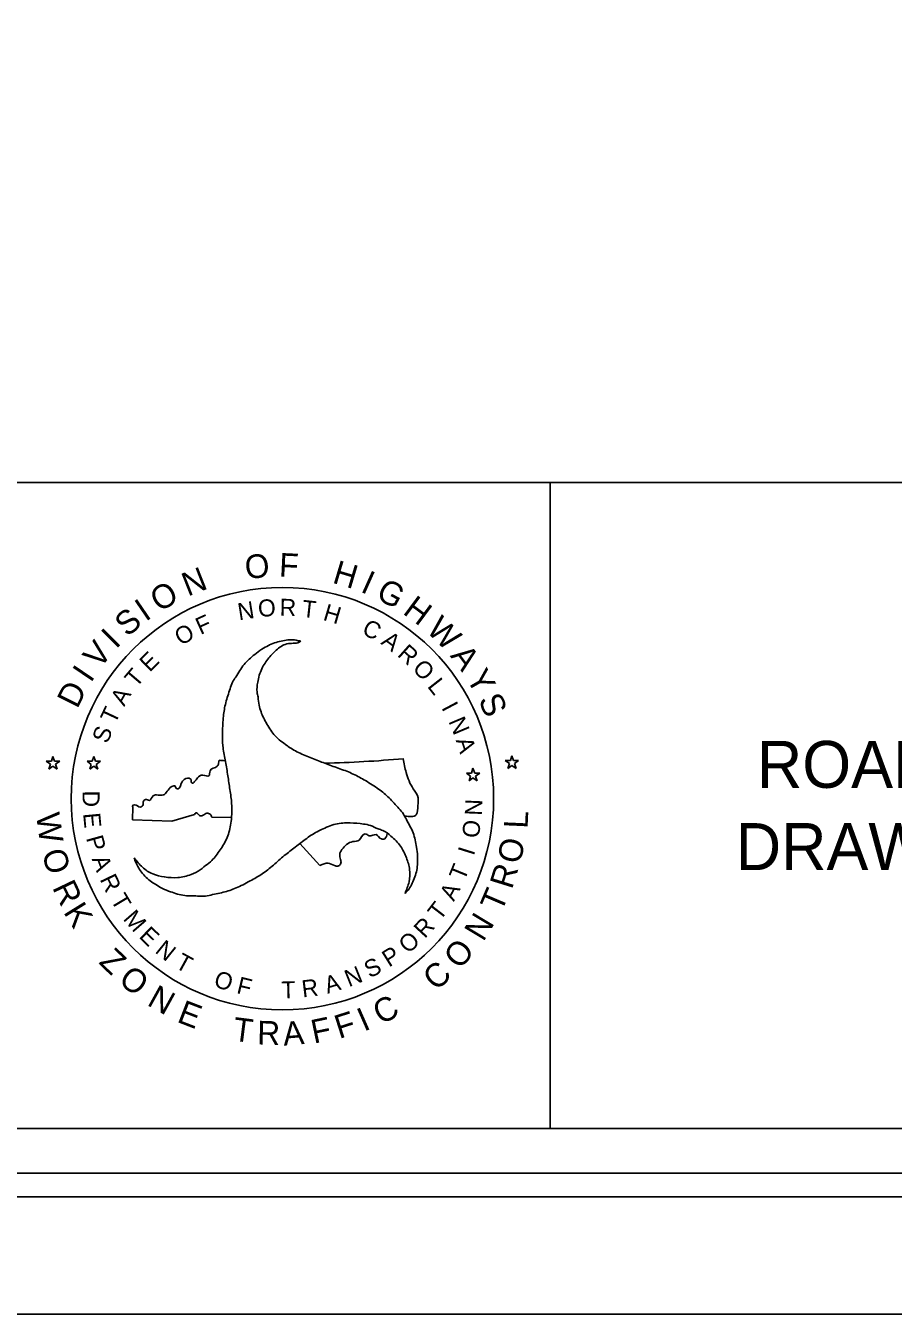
# Model space of a CAD drawing. Extents: x 198 to 2213, y -571 to 529.
# Drawn here: x 1502.9 to 1687.6, y -570.9 to -296.6 of the extents above; entities that cross this region are included whole.
import ezdxf

# ---------------------------------------------------------------- set-up
doc = ezdxf.new("R2010")
doc.units = 0
for name, color, linetype in [('P_RDY_Dimension', 7, 'Continuous'), ('Sheet Data Field CELL', 7, 'Continuous'), ('Sheet PE Seal CELL', 7, 'Continuous'), ('z - Construction', 7, 'Continuous')]:
    doc.layers.add(name, color=color, linetype=linetype)

msp = doc.modelspace()

# ---------------------------------------------------------------- linework, layer by layer
at = {"layer": 'P_RDY_Dimension'}
for p, q in [((1508.64, -452.14), (1508.32, -453.15)), ((1509, -453.15), (1508.64, -452.14)), ((1517.32, -452.16), (1517, -453.16)), ((1517.68, -453.16), (1517.32, -452.16)), ((1606.36, -452), (1606.04, -453.01)), ((1606.72, -453.01), (1606.36, -452)), ((1507.23, -453.15), (1508.12, -453.79)), ((1508.32, -453.15), (1507.23, -453.15)), ((1508.12, -453.79), (1507.8, -454.83)), ((1507.8, -454.83), (1508.64, -454.19)), ((1508.64, -454.19), (1509.53, -454.83)), ((1508.64, -454.19), (1509.52, -454.83)), ((1510.08, -453.15), (1509, -453.15)), ((1509.2, -453.79), (1510.09, -453.15)), ((1509.2, -453.79), (1510.08, -453.15)), ((1509.53, -454.83), (1509.2, -453.79)), ((1509.52, -454.83), (1509.2, -453.79)), ((1517, -453.16), (1515.91, -453.16)), ((1515.91, -453.16), (1516.8, -453.8)), ((1516.8, -453.8), (1516.48, -454.85)), ((1516.48, -454.85), (1517.32, -454.2)), ((1517.32, -454.2), (1518.2, -454.85)), ((1518.76, -453.16), (1517.68, -453.16)), ((1517.88, -453.8), (1518.76, -453.16)), ((1518.2, -454.85), (1517.88, -453.8)), ((1598.08, -454.65), (1597.76, -455.65)), ((1598.45, -455.65), (1598.08, -454.65)), ((1606.04, -453.01), (1604.96, -453.01)), ((1604.96, -453.01), (1605.84, -453.65)), ((1605.84, -453.65), (1605.52, -454.69)), ((1605.52, -454.69), (1606.36, -454.05)), ((1606.36, -454.05), (1607.25, -454.69)), ((1607.81, -453.01), (1606.72, -453.01)), ((1606.93, -453.65), (1607.81, -453.01)), ((1607.25, -454.69), (1606.93, -453.65)), ((1597.76, -455.65), (1596.68, -455.65)), ((1596.68, -455.65), (1597.56, -456.29)), ((1597.56, -456.29), (1597.24, -457.34)), ((1597.24, -457.34), (1598.08, -456.69)), ((1598.08, -456.69), (1598.97, -457.34)), ((1599.53, -455.65), (1598.45, -455.65)), ((1598.65, -456.29), (1599.53, -455.65)), ((1598.97, -457.34), (1598.65, -456.29)), ((1525.56, -465.59), (1525.64, -462.94)), ((1533.95, -465.9), (1525.56, -465.59)), ((1538.76, -464.49), (1533.95, -465.9)), ((1542.46, -465.05), (1546.67, -465.09)), ((1561.21, -470.67), (1565.51, -475.34))]:
    msp.add_line(p, q, dxfattribs=at)
for start, end in [(265.6785, 265.9762), (271.2035, 275.3236)]:
    msp.add_arc((1561.6, -220.41), 233.19, start, end, dxfattribs=at)
for points in [[(1525.97, -473.7), (1527.72, -475.72), (1529.89, -477.11), (1532.39, -477.76), (1535.21, -477.92), (1538.08, -477.25), (1539.99, -476.28), (1540.79, -475.64), (1542.19, -474.54), (1543.18, -473.46), (1544.84, -471.1), (1546.13, -468.31), (1546.67, -465.11), (1546.69, -464.84), (1546.67, -461.84), (1546.27, -458.8), (1545.84, -455.88), (1545.3, -452.85), (1544.82, -449.84), (1544.76, -446.91), (1544.95, -443.56), (1545.44, -440.69), (1546.37, -437.73), (1546.88, -436.34), (1547.58, -435.21), (1549.33, -432.55), (1551.61, -430.41), (1553.11, -429.28), (1554.53, -428.52), (1554.78, -428.39), (1557.62, -427.48), (1560.41, -427.37), (1561.35, -427.61)], [(1561.43, -427.53), (1561.35, -427.61), (1558.78, -428.09), (1556.44, -429.3), (1554.64, -431.13), (1553.11, -433.46), (1552.25, -436.31), (1552.12, -438.43), (1552.31, -439.45), (1552.55, -441.22), (1552.95, -442.62), (1554.21, -445.22), (1555.96, -447.75), (1558.48, -449.81), (1558.7, -449.97), (1561.27, -451.45), (1564.15, -452.63), (1566.88, -453.7), (1569.76, -454.75), (1572.6, -455.88), (1575.18, -457.27), (1578, -459.1), (1580.22, -460.95), (1582.32, -463.23), (1583.28, -464.39), (1583.9, -465.57), (1585.35, -468.39), (1586.05, -471.45), (1586.29, -473.33), (1586.24, -474.94), (1586.24, -475.21), (1585.57, -478.13), (1584.25, -480.6), (1583.61, -481.27)], [(1525.64, -462.94), (1525.56, -462.68), (1526.01, -462.4), (1527.26, -462.91), (1527.88, -462.37), (1527.85, -461.83), (1528.36, -461.3), (1529.2, -461.47), (1529.97, -460.5), (1530.67, -460.31), (1532.17, -460.31), (1533.95, -458.53), (1534.69, -458.42), (1534.88, -458.9), (1535.34, -458.98), (1536.13, -457.51), (1536.32, -457.31), (1537.68, -456.75), (1538.05, -457.03), (1538.16, -457.68), (1538.36, -457.79), (1538.81, -457.48), (1539.43, -456.69), (1540.56, -456.1), (1541.86, -456.27), (1542.09, -455.19), (1543.62, -454.18), (1543.93, -453.56), (1544.01, -452.93)], [(1583.53, -464.82), (1586, -464.52), (1586.37, -462.57), (1586.4, -460.93), (1585.38, -459.04), (1583.85, -455.56), (1583.23, -452.59)], [(1583.61, -481.27), (1584.47, -478.8), (1584.6, -476.2), (1583.9, -473.7), (1582.64, -471.21), (1580.62, -469.06), (1578.86, -467.88), (1577.86, -467.53), (1576.25, -466.83), (1574.77, -466.51), (1571.93, -466.27), (1568.84, -466.54), (1565.81, -467.69), (1565.57, -467.8), (1562.99, -469.33), (1560.55, -471.18), (1558.21, -473), (1555.88, -474.99), (1553.49, -476.92), (1550.99, -478.43), (1547.98, -479.96), (1545.27, -480.95), (1542.27, -481.62), (1540.76, -481.89), (1539.45, -481.84), (1536.31, -481.68), (1533.27, -480.77), (1531.56, -480.04), (1530.19, -479.15), (1529.95, -479.02), (1527.74, -477.01), (1526.27, -474.64), (1525.97, -473.7)], [(1542.46, -465.05), (1542.12, -464.41), (1541.44, -464.21), (1540.51, -464.69), (1539.83, -464.66), (1539.07, -464.09), (1538.76, -464.49)], [(1565.51, -475.34), (1567.21, -474.83), (1568.62, -475.37), (1569.3, -475.48), (1569.87, -475.06), (1569.7, -472.94), (1570.18, -471.95), (1572.47, -470.25), (1573.88, -469.94), (1574.93, -468.64), (1575.35, -468.67), (1576, -469.04), (1577.44, -468.76), (1578.6, -469.69), (1579.28, -469.63), (1579.82, -468.57)]]:
    msp.add_spline(points, degree=3, dxfattribs=at)
at = {"layer": 'Sheet Data Field CELL'}
for points in [[(197.66, -570.86), (1885.65, -570.86), (1885.65, 529.13), (197.66, 529.13)], [(197.66, 529.13), (1885.65, 529.13), (1885.65, -570.86), (197.66, -570.86)]]:
    msp.add_lwpolyline(points, close=True, dxfattribs=at)
at = {"layer": 'Sheet PE Seal CELL'}
for p, q in [((938.42, -540.86), (1850.37, -540.86)), ((370.94, -545.86), (1850.37, -545.86))]:
    msp.add_line(p, q, dxfattribs=at)
for points in [[(1500.5, -393.81), (1614.51, -393.81), (1614.51, -531.31), (1500.5, -531.31)], [(1850.5, -393.81), (1614.51, -393.81), (1614.51, -531.31), (1850.5, -531.31)]]:
    msp.add_lwpolyline(points, close=True, dxfattribs=at)
at = {"layer": 'z - Construction'}
msp.add_circle((1557.51, -461.11), 44.97, dxfattribs=at)

# ---------------------------------------------------------------- texts
at = {"layer": 'P_RDY_Dimension'}
for s, height, rotation, p in [('O', 5.04, 5.7649, (1549.76, -414.38)), ('F', 5.04, 357.2575, (1556.72, -413.82)), ('H', 5.04, 343.454, (1567.95, -415.11)), ('N', 5.04, 21.5861, (1537.36, -418.11)), ('I', 5.04, 335.804, (1573.94, -416.98)), ('O', 5.04, 30.0935, (1531.25, -421.48)), ('G', 5.04, 331.5167, (1577.18, -418.37)), ('I', 5.04, 34.3808, (1528.38, -423.51)), ('N', 3.63, 9.0227, (1548.28, -423.16)), ('O', 3.63, 3.9446, (1552.43, -422.44)), ('R', 3.63, 358.8665, (1556.9, -422.17)), ('H', 3.63, 343.6322, (1565.98, -423.03)), ('H', 5.04, 323.4632, (1582.93, -421.62)), ('S', 5.04, 40.5848, (1524.51, -426.82)), ('F', 3.63, 24.2569, (1540.06, -426.28)), ('W', 5.04, 315.8133, (1587.92, -425.42)), ('I', 5.04, 44.8722, (1522.06, -429.35)), ('O', 3.63, 29.335, (1535.85, -428.63)), ('C', 3.63, 333.4761, (1574.21, -425.95)), ('V', 5.04, 51.5806, (1518.61, -433.64)), ('A', 3.63, 323.3199, (1578.31, -428.07)), ('E', 3.63, 44.5692, (1529.24, -434.31)), ('R', 3.63, 318.2418, (1581.81, -430.63)), ('A', 5.04, 306.7762, (1593.11, -430.72)), ('I', 5.04, 55.8679, (1516.69, -436.59)), ('T', 3.63, 49.6473, (1526.38, -437.63)), ('O', 3.63, 313.1637, (1585.01, -433.54)), ('Y', 5.04, 299.7484, (1596.52, -435.37)), ('L', 3.63, 308.0856, (1588.23, -437.22)), ('D', 5.04, 63.459, (1513.83, -442.12)), ('A', 3.63, 59.8035, (1523.82, -441.61)), ('S', 5.04, 293.2249, (1599.16, -440.02)), ('T', 3.63, 64.8816, (1521.88, -445.4)), ('I', 3.63, 297.9295, (1591.28, -441.72)), ('N', 3.63, 292.8514, (1592.8, -444.63)), ('S', 3.63, 69.9597, (1520.3, -449.55)), ('A', 3.63, 287.7733, (1594.39, -448.68)), ('D', 3.63, 270.272, (1514.95, -459.4)), ('N', 3.63, 87.733, (1599.95, -464.77)), ('E', 3.63, 275.3501, (1515.07, -464.26)), ('O', 3.63, 82.9269, (1599.32, -469.63)), ('P', 3.63, 285.5063, (1515.67, -469.47)), ('I', 3.63, 72.7707, (1598.24, -473.39)), ('A', 3.63, 290.5843, (1516.87, -473.93)), ('R', 3.63, 295.6624, (1518.55, -478.26)), ('T', 3.63, 67.6926, (1596.24, -478.78)), ('A', 3.63, 62.6145, (1594.01, -483.12)), ('T', 3.63, 300.7405, (1520.83, -482.67)), ('M', 3.63, 310.8967, (1523.44, -486.76)), ('T', 3.63, 52.4584, (1591.06, -487.26)), ('R', 3.63, 47.3803, (1587.81, -491.01)), ('E', 3.63, 315.9748, (1526.78, -490.58)), ('O', 3.63, 42.3022, (1584.28, -494.27)), ('N', 3.63, 321.0529, (1530.2, -493.74)), ('P', 3.63, 32.146, (1580.2, -497.09)), ('T', 3.63, 331.209, (1534.45, -496.98)), ('S', 3.63, 27.068, (1576.08, -499.4)), ('O', 3.63, 341.3652, (1542.66, -501)), ('F', 3.63, 346.4433, (1547.58, -502.48)), ('A', 3.63, 16.9118, (1567.09, -502.66)), ('N', 3.63, 21.9899, (1571.66, -501.27)), ('T', 3.63, 1.6775, (1557.34, -503.67)), ('R', 3.63, 6.7556, (1561.83, -503.43))]:
    msp.add_text(s, height=height, rotation=rotation, dxfattribs=at).set_placement(p)
at = {"layer": 'Sheet PE Seal CELL'}
for s, p in [('ROADWAY STANDARD ', (1658.54, -458.81)), ('DRAWINGS & LEGEND', (1654.04, -476.31))]:
    msp.add_text(s, height=10, dxfattribs=at).set_placement(p)
at = {"layer": 'z - Construction'}
for s, height, rotation, p in [('T', 3.63, 353.7884, (1561.53, -422.39)), ('W', 5.04, 278.15, (1505.02, -464.48)), ('L', 5.04, 87.429, (1609.7, -467.55)), ('O', 5.04, 78.9896, (1608.19, -475.15)), ('O', 5.04, 287.1147, (1506.19, -472.62)), ('R', 5.04, 72.7519, (1606.37, -480.57)), ('R', 5.04, 295.5541, (1508.43, -480.02)), ('T', 5.04, 66.881, (1604.12, -485.47)), ('K', 5.04, 301.7918, (1510.78, -485.24)), ('N', 5.04, 58.892, (1600.28, -491.71)), ('Z', 5.04, 316.1688, (1518.23, -496.09)), ('O', 5.04, 50.4526, (1595.33, -497.65)), ('C', 5.04, 43.0807, (1590.32, -502.2)), ('O', 5.04, 322.5233, (1522.35, -500.22)), ('N', 5.04, 330.9626, (1528.47, -504.96)), ('E', 5.04, 338.9517, (1534.85, -508.57)), ('C', 5.04, 28.0033, (1578.5, -509.33)), ('F', 5.04, 17.7627, (1569.6, -512.29)), ('I', 5.04, 23.7503, (1574.87, -510.75)), ('T', 5.04, 352.6948, (1546.77, -512.59)), ('R', 5.04, 358.5656, (1552.09, -513.42)), ('A', 5.04, 4.8034, (1557.81, -513.7)), ('F', 5.04, 11.7751, (1564.19, -513.27))]:
    msp.add_text(s, height=height, rotation=rotation, dxfattribs=at).set_placement(p)

doc.saveas('drawing.dxf')
